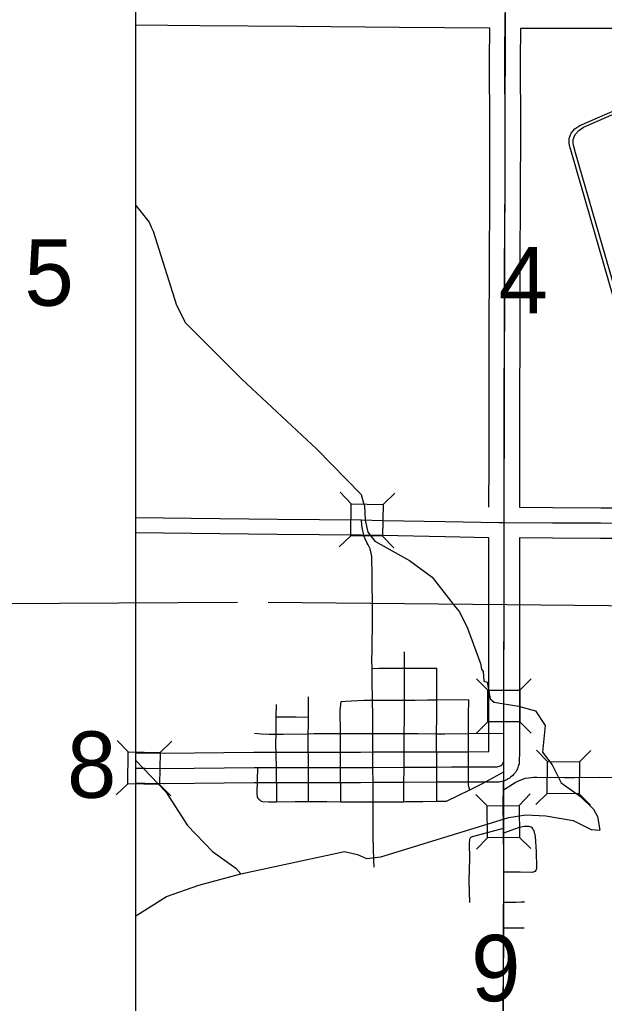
# Model space of a CAD drawing. Extents: x -2251611 to -2054719, y -2227156 to -2099355.
# Drawn here: x -2148163 to -2142114, y -2140286 to -2130114 of the extents above; entities that cross this region are included whole.
import ezdxf

# ---------------------------------------------------------------- set-up
doc = ezdxf.new("R2010")
doc.units = 0
for name, color, linetype in [('dsnTextNote', 7, 'Continuous'), ('tdCoCityStreetMajor', 7, 'Continuous'), ('tdCoCityStreetMinor', 7, 'Continuous'), ('tdCoHydroRiver', 7, 'Continuous'), ('tdCoSecRteBand', 7, 'Continuous'), ('tdCoSectLinePart', 7, 'Continuous'), ('tdCoSectNmbr', 7, 'Continuous'), ('tdCoShieldCoRteHrd', 7, 'Continuous'), ('tdCoStrucSec', 7, 'Continuous'), ('tdCoSurfAsphalt', 7, 'Continuous'), ('tdCoSurfAsphaltUnbanded', 7, 'Continuous'), ('tdCoSurfConcUnbanded', 7, 'Continuous'), ('tdCoSurfGravel', 7, 'Continuous'), ('tdCoTwpBndryShd', 7, 'Continuous')]:
    doc.layers.add(name, color=color, linetype=linetype)

msp = doc.modelspace()

# ---------------------------------------------------------------- linework, layer by layer
at = {"layer": 'dsnTextNote'}
msp.add_lwpolyline([(-2138305, -2118110), (-2124096, -2118110), (-2124096, -2144316), (-2146960, -2144316), (-2146960, -2118110), (-2138305, -2118110)], dxfattribs=at)
at = {"layer": 'tdCoCityStreetMajor'}
for p, q in [((-2143748, -2138195), (-2143504, -2138077)), ((-2143847, -2138196), (-2143748, -2138195))]:
    msp.add_line(p, q, dxfattribs=at)
for points in [[(-2144514, -2136288), (-2144515, -2135811), (-2144518, -2135719), (-2144520, -2135664), (-2144527, -2135630), (-2144538, -2135587), (-2144547, -2135566), (-2144556, -2135546), (-2144567, -2135527), (-2144589, -2135484), (-2144598, -2135458), (-2144605, -2135432), (-2144616, -2135383), (-2144622, -2135344), (-2144627, -2135288)], [(-2144517, -2136635), (-2144514, -2136315), (-2144514, -2136288)], [(-2144510, -2137496), (-2144510, -2137315), (-2144513, -2137152), (-2144516, -2136945), (-2144517, -2136823), (-2144518, -2136742), (-2144517, -2136635)], [(-2144506, -2138203), (-2144507, -2138005), (-2144508, -2137846), (-2144510, -2137621), (-2144510, -2137496)], [(-2143504, -2138077), (-2143382, -2138018), (-2143155, -2137891)], [(-2144506, -2138203), (-2144340, -2138203), (-2144188, -2138201), (-2144172, -2138200)], [(-2144172, -2138200), (-2143993, -2138198), (-2143847, -2138196)]]:
    msp.add_lwpolyline(points, dxfattribs=at)
at = {"layer": 'tdCoCityStreetMinor'}
for p, q in [((-2143848, -2136962), (-2143847, -2136819)), ((-2145175, -2137326), (-2145173, -2137117)), ((-2143943, -2137149), (-2143848, -2137148)), ((-2144184, -2137495), (-2144183, -2137346)), ((-2144186, -2137844), (-2144185, -2137683)), ((-2145173, -2138200), (-2145175, -2137847)), ((-2144187, -2138026), (-2144186, -2137844)), ((-2143847, -2138031), (-2143848, -2137843)), ((-2143847, -2138196), (-2143847, -2138031)), ((-2143155, -2139507), (-2142943, -2139507))]:
    msp.add_line(p, q, dxfattribs=at)
for points in [[(-2144183, -2137346), (-2144182, -2137150), (-2144182, -2137014), (-2144181, -2136819), (-2144180, -2136651)], [(-2144517, -2136823), (-2144447, -2136820), (-2144181, -2136819), (-2144116, -2136819), (-2143847, -2136819)], [(-2143848, -2137148), (-2143848, -2136967), (-2143848, -2136962)], [(-2145510, -2137503), (-2145508, -2137389), (-2145508, -2137324), (-2145507, -2137196)], [(-2144842, -2137847), (-2144844, -2137557), (-2144845, -2137497), (-2144848, -2137255), (-2144836, -2137164)], [(-2144836, -2137164), (-2144792, -2137160), (-2144603, -2137153), (-2144513, -2137152)], [(-2144513, -2137152), (-2144513, -2137152), (-2144380, -2137150), (-2144182, -2137150), (-2144072, -2137151), (-2143943, -2137149)], [(-2143848, -2137843), (-2143849, -2137530), (-2143849, -2137498), (-2143848, -2137316), (-2143848, -2137148)], [(-2143848, -2137148), (-2143848, -2137148), (-2143712, -2137146), (-2143517, -2137149)], [(-2143519, -2137842), (-2143520, -2137552), (-2143520, -2137496), (-2143519, -2137306), (-2143517, -2137149)], [(-2145508, -2137324), (-2145482, -2137324), (-2145303, -2137325), (-2145175, -2137326)], [(-2145177, -2137498), (-2145175, -2137405), (-2145175, -2137326)], [(-2145733, -2137491), (-2145663, -2137499), (-2145581, -2137504), (-2145510, -2137503)], [(-2145507, -2137847), (-2145511, -2137596), (-2145510, -2137503)], [(-2145510, -2137503), (-2145438, -2137502), (-2145177, -2137498), (-2145119, -2137497), (-2144845, -2137497), (-2144747, -2137497), (-2144510, -2137496), (-2144339, -2137495), (-2144184, -2137495), (-2144041, -2137496), (-2143849, -2137498), (-2143765, -2137499), (-2143520, -2137496), (-2143152, -2137491)], [(-2145175, -2137847), (-2145178, -2137564), (-2145177, -2137498)], [(-2144185, -2137683), (-2144184, -2137539), (-2144184, -2137495)], [(-2145678, -2138185), (-2145687, -2138178), (-2145696, -2138166), (-2145702, -2138153), (-2145706, -2138117), (-2145698, -2137848)], [(-2145502, -2138201), (-2145502, -2138163), (-2145507, -2137847), (-2145507, -2137847)], [(-2144840, -2138202), (-2144840, -2138174), (-2144842, -2137847)], [(-2143504, -2138077), (-2143516, -2138049), (-2143519, -2138027), (-2143519, -2137842)], [(-2144188, -2138201), (-2144188, -2138154), (-2144187, -2138101), (-2144187, -2138026)], [(-2145678, -2138185), (-2145676, -2138187), (-2145664, -2138195), (-2145650, -2138200), (-2145587, -2138202), (-2145502, -2138201), (-2145314, -2138200), (-2145173, -2138200), (-2144985, -2138200), (-2144840, -2138202), (-2144705, -2138203), (-2144506, -2138203)], [(-2144501, -2138685), (-2144505, -2138558), (-2144506, -2138203)], [(-2142864, -2138931), (-2142856, -2138931), (-2142846, -2138928), (-2142836, -2138924), (-2142827, -2138918), (-2142820, -2138909), (-2142815, -2138900), (-2142812, -2138889), (-2142812, -2138879), (-2142816, -2138721), (-2142826, -2138561), (-2142840, -2138502), (-2142845, -2138491), (-2142850, -2138484), (-2142852, -2138481), (-2142860, -2138472), (-2142870, -2138465), (-2142881, -2138460), (-2142893, -2138457), (-2142906, -2138457), (-2142943, -2138458), (-2143006, -2138471), (-2143109, -2138509), (-2143156, -2138527)], [(-2143501, -2138577), (-2143495, -2138570), (-2143487, -2138564), (-2143478, -2138560), (-2143374, -2138532), (-2143156, -2138476)], [(-2143506, -2139243), (-2143512, -2139018), (-2143506, -2138793), (-2143510, -2138630), (-2143507, -2138595), (-2143505, -2138586), (-2143501, -2138577)], [(-2144494, -2138878), (-2144498, -2138802), (-2144501, -2138685)], [(-2143154, -2138925), (-2142984, -2138928), (-2142864, -2138931)], [(-2143155, -2139242), (-2143126, -2139241), (-2143067, -2139240), (-2143030, -2139239), (-2142975, -2139238), (-2142940, -2139237)]]:
    msp.add_lwpolyline(points, dxfattribs=at)
at = {"layer": 'tdCoHydroRiver'}
for points in [[(-2146960, -2132034), (-2146823, -2132209), (-2146798, -2132267), (-2146781, -2132300), (-2146539, -2133067), (-2146447, -2133250), (-2145863, -2133833), (-2145087, -2134557), (-2144629, -2135023), (-2144604, -2135115), (-2144595, -2135140), (-2144587, -2135290), (-2144562, -2135415), (-2144487, -2135506), (-2144128, -2135706), (-2143895, -2135881), (-2143653, -2136189), (-2143611, -2136239), (-2143528, -2136406), (-2143394, -2136772), (-2143386, -2136830), (-2143369, -2136855), (-2143361, -2136955), (-2143327, -2136964), (-2143294, -2137139), (-2143252, -2137172), (-2143002, -2137213), (-2142827, -2137263), (-2142727, -2137413), (-2142752, -2137688), (-2142652, -2137821), (-2142560, -2138005), (-2142360, -2138146), (-2142226, -2138279), (-2142185, -2138354), (-2142159, -2138496)], [(-2146960, -2137776), (-2146651, -2138099), (-2146426, -2138449), (-2146167, -2138716), (-2145925, -2138890), (-2145875, -2138949)], [(-2145875, -2138949), (-2144801, -2138715), (-2144667, -2138748), (-2144576, -2138789), (-2144426, -2138773), (-2143101, -2138363), (-2142926, -2138338), (-2142718, -2138346), (-2142435, -2138396), (-2142251, -2138488), (-2142159, -2138496)], [(-2146960, -2139383), (-2146642, -2139183), (-2146309, -2139066), (-2145875, -2138949)]]:
    msp.add_lwpolyline(points, dxfattribs=at)
at = {"layer": 'tdCoSecRteBand'}
for points in [[(-2143309, -2135154), (-2143309, -2135062), (-2143309, -2135062), (-2143309, -2135062), (-2143307, -2134783), (-2143307, -2134090), (-2143307, -2134090), (-2143307, -2134089), (-2143305, -2133342), (-2143303, -2132662), (-2143303, -2132662), (-2143303, -2132662), (-2143300, -2131924), (-2143298, -2131238), (-2143301, -2130532), (-2143301, -2130531), (-2143301, -2130530), (-2143299, -2130203), (-2143769, -2130199), (-2143769, -2130199), (-2143769, -2130199), (-2144236, -2130194), (-2145296, -2130186), (-2145296, -2130186), (-2145296, -2130186), (-2146300, -2130176), (-2146960, -2130170)], [(-2141984, -2130206), (-2142615, -2130205), (-2142882, -2130205), (-2142882, -2130205), (-2142883, -2130205), (-2142982, -2130205), (-2142982, -2130205), (-2142984, -2130531), (-2142981, -2131238), (-2142981, -2131238), (-2142981, -2131239), (-2142983, -2131925), (-2142983, -2131925), (-2142983, -2131925), (-2142987, -2132663), (-2142988, -2133343), (-2142988, -2133343), (-2142988, -2133343), (-2142991, -2134090), (-2142991, -2134784), (-2142991, -2134784), (-2142991, -2134785), (-2142992, -2135063), (-2142992, -2135156), (-2142992, -2135156), (-2142650, -2135158), (-2142649, -2135158), (-2142649, -2135158), (-2142151, -2135161), (-2142151, -2135161), (-2142150, -2135161), (-2141863, -2135163)], [(-2146960, -2137697), (-2146888, -2137696), (-2146888, -2137696), (-2146886, -2137696), (-2146883, -2137696), (-2146862, -2137696), (-2146667, -2137700), (-2145739, -2137689), (-2145738, -2137689), (-2145738, -2137689), (-2145699, -2137689), (-2145507, -2137689), (-2145175, -2137689), (-2144843, -2137688), (-2144638, -2137688), (-2144509, -2137687), (-2144186, -2137686), (-2143848, -2137685), (-2143696, -2137684), (-2143696, -2137684), (-2143696, -2137684), (-2143520, -2137684), (-2143310, -2137683), (-2143310, -2137681), (-2143310, -2137491), (-2143310, -2137231), (-2143310, -2137199), (-2143310, -2136885), (-2143310, -2136885), (-2143310, -2136885), (-2143309, -2136195), (-2143309, -2135484), (-2143309, -2135472), (-2143309, -2135472), (-2143309, -2135472), (-2143309, -2135471), (-2143762, -2135463), (-2143763, -2135463), (-2143763, -2135463), (-2144412, -2135450), (-2144629, -2135446), (-2145497, -2135437), (-2146389, -2135427), (-2146960, -2135421)], [(-2141865, -2135480), (-2142152, -2135478), (-2142651, -2135475), (-2142992, -2135473), (-2142992, -2135484), (-2142992, -2136195), (-2142992, -2136195), (-2142992, -2136196), (-2142993, -2136886), (-2142993, -2137199), (-2142993, -2137231), (-2142993, -2137491), (-2142993, -2137684), (-2142993, -2137686), (-2142993, -2137688), (-2142996, -2137787), (-2142996, -2137810), (-2143004, -2137833), (-2143008, -2137846), (-2143013, -2137860), (-2143020, -2137873), (-2143027, -2137885), (-2143034, -2137898), (-2143043, -2137909), (-2143052, -2137920), (-2143062, -2137931), (-2143073, -2137941), (-2143084, -2137949), (-2143095, -2137959), (-2143108, -2137966), (-2143120, -2137973), (-2143133, -2137980), (-2143147, -2137985), (-2143160, -2137989), (-2143174, -2137994), (-2143188, -2137996), (-2143202, -2137998), (-2143213, -2137999), (-2143224, -2138000), (-2143519, -2138000), (-2143695, -2138001), (-2143847, -2138001), (-2144185, -2138003), (-2144508, -2138004), (-2144637, -2138005), (-2144637, -2138005), (-2144637, -2138005), (-2144842, -2138005), (-2145175, -2138005), (-2145507, -2138006), (-2145698, -2138006), (-2145737, -2138006), (-2146665, -2138016), (-2146668, -2138016), (-2146670, -2138016), (-2146867, -2138013), (-2146886, -2138013), (-2146960, -2138013)]]:
    msp.add_lwpolyline(points, dxfattribs=at)
at = {"layer": 'tdCoSectLinePart'}
for points in [[(-2148366, -2136153), (-2145908, -2136137)], [(-2145592, -2136138), (-2140657, -2136186)]]:
    msp.add_lwpolyline(points, dxfattribs=at)
at = {"layer": 'tdCoShieldCoRteHrd'}
for points in [[(-2142022, -2132977), (-2142454, -2131483), (-2142475, -2131414), (-2142479, -2131383), (-2142479, -2131342), (-2142456, -2131287), (-2142418, -2131242), (-2142367, -2131207), (-2141484, -2130825), (-2141444, -2130816), (-2141389, -2130812), (-2141334, -2130816), (-2141295, -2130825), (-2140411, -2131207), (-2140361, -2131242), (-2140322, -2131287), (-2140300, -2131342), (-2140300, -2131383), (-2140304, -2131414), (-2140324, -2131483), (-2140757, -2132977)], [(-2141991, -2132944), (-2142412, -2131490), (-2142431, -2131424), (-2142435, -2131394), (-2142435, -2131354), (-2142414, -2131302), (-2142377, -2131259), (-2142328, -2131225), (-2141480, -2130858), (-2141442, -2130850), (-2141389, -2130845), (-2141337, -2130850), (-2141298, -2130858), (-2140451, -2131225), (-2140402, -2131259), (-2140365, -2131302), (-2140344, -2131354), (-2140344, -2131394), (-2140347, -2131424), (-2140367, -2131490), (-2140788, -2132944)]]:
    msp.add_lwpolyline(points, close=True, dxfattribs=at)
at = {"layer": 'tdCoStrucSec'}
for p, q in [((-2144732, -2135120), (-2144847, -2135001)), ((-2144401, -2135127), (-2144282, -2135012)), ((-2144738, -2135451), (-2144857, -2135565)), ((-2144408, -2135457), (-2144293, -2135576)), ((-2143319, -2137047), (-2143435, -2136930)), ((-2142988, -2137047), (-2142871, -2136930)), ((-2143319, -2137377), (-2143435, -2137494)), ((-2142988, -2137377), (-2142871, -2137494)), ((-2147039, -2137686), (-2147154, -2137567)), ((-2146709, -2137692), (-2146590, -2137577)), ((-2142701, -2137785), (-2142817, -2137667)), ((-2142370, -2137788), (-2142252, -2137672)), ((-2147045, -2138017), (-2147164, -2138131)), ((-2146715, -2138022), (-2146600, -2138141)), ((-2143326, -2138243), (-2143444, -2138128)), ((-2142996, -2138239), (-2142880, -2138121)), ((-2142704, -2138116), (-2142822, -2138231)), ((-2142373, -2138119), (-2142257, -2138237)), ((-2143322, -2138574), (-2143438, -2138692)), ((-2142992, -2138570), (-2142874, -2138686))]:
    msp.add_line(p, q, dxfattribs=at)
for points in [[(-2144732, -2135120), (-2144401, -2135127), (-2144408, -2135457), (-2144738, -2135451)], [(-2143319, -2137377), (-2143319, -2137047), (-2142988, -2137047), (-2142988, -2137377)], [(-2147039, -2137686), (-2146709, -2137692), (-2146715, -2138022), (-2147045, -2138017)], [(-2142701, -2137785), (-2142370, -2137788), (-2142373, -2138119), (-2142704, -2138116)], [(-2143322, -2138574), (-2143326, -2138243), (-2142996, -2138239), (-2142992, -2138570)]]:
    msp.add_lwpolyline(points, close=True, dxfattribs=at)
at = {"layer": 'tdCoSurfAsphalt'}
for points in [[(-2143150, -2135314), (-2143150, -2135062), (-2143149, -2134784), (-2143149, -2134090), (-2143146, -2133342), (-2143145, -2132663), (-2143141, -2131924), (-2143140, -2131238), (-2143142, -2130531), (-2143140, -2130046)], [(-2143152, -2137491), (-2143152, -2137231), (-2143152, -2137199), (-2143152, -2136885), (-2143150, -2136195), (-2143150, -2135484), (-2143150, -2135314)], [(-2143154, -2137783), (-2143152, -2137684), (-2143152, -2137491)], [(-2146960, -2137855), (-2146886, -2137854), (-2146886, -2137854), (-2146864, -2137855), (-2146667, -2137858), (-2145738, -2137848), (-2145698, -2137848)], [(-2145698, -2137848), (-2145507, -2137847), (-2145175, -2137847), (-2144842, -2137847), (-2144637, -2137846), (-2144508, -2137846), (-2144186, -2137844), (-2143848, -2137843), (-2143696, -2137842), (-2143519, -2137842), (-2143224, -2137841), (-2143211, -2137839), (-2143197, -2137835), (-2143185, -2137828), (-2143174, -2137819), (-2143165, -2137808), (-2143159, -2137796), (-2143154, -2137783)]]:
    msp.add_lwpolyline(points, dxfattribs=at)
at = {"layer": 'tdCoSurfAsphaltUnbanded'}
for points in [[(-2143159, -2140573), (-2143159, -2140259), (-2143155, -2139674), (-2143155, -2139507), (-2143155, -2139320), (-2143155, -2139242), (-2143154, -2138925), (-2143153, -2138767), (-2143156, -2138527), (-2143156, -2138476), (-2143159, -2138212), (-2143158, -2138077), (-2143155, -2137891), (-2143154, -2137783)], [(-2143158, -2138077), (-2143035, -2138004), (-2143010, -2137990), (-2142983, -2137978), (-2142956, -2137967), (-2142928, -2137959), (-2142900, -2137953), (-2142871, -2137950), (-2142842, -2137948), (-2142813, -2137949), (-2142527, -2137952), (-2142422, -2137951)]]:
    msp.add_lwpolyline(points, dxfattribs=at)
at = {"layer": 'tdCoSurfConcUnbanded'}
msp.add_lwpolyline([(-2142422, -2137951), (-2142168, -2137947), (-2141865, -2137951)], dxfattribs=at)
at = {"layer": 'tdCoSurfGravel'}
for points in [[(-2146960, -2135262), (-2146387, -2135268), (-2145495, -2135278), (-2144627, -2135288), (-2144409, -2135292), (-2143760, -2135305), (-2143206, -2135314), (-2143150, -2135314)], [(-2143150, -2135314), (-2142650, -2135316), (-2142152, -2135319), (-2141864, -2135321), (-2141864, -2135321)]]:
    msp.add_lwpolyline(points, dxfattribs=at)
at = {"layer": 'tdCoTwpBndryShd'}
msp.add_lwpolyline([(-2143082, -2118110), (-2143089, -2119427), (-2143116, -2124764), (-2143141, -2130046), (-2143152, -2135314), (-2143161, -2140573), (-2143174, -2144316)], dxfattribs=at)

# ---------------------------------------------------------------- texts
at = {"layer": 'tdCoSectNmbr'}
for s, rotation, p in [('5', 0.0178, (-2148113, -2133072)), ('4', 0.0185, (-2143206, -2133150)), ('8', 0.0177, (-2147673, -2138161)), ('9', 0.0185, (-2143492, -2140265))]:
    msp.add_text(s, height=686, rotation=rotation, dxfattribs=at).set_placement(p)

doc.saveas('drawing.dxf')
